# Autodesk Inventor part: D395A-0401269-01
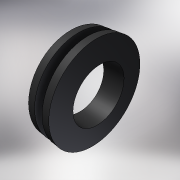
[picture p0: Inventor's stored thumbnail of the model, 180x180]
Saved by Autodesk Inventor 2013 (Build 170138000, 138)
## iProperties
Created: 2002-06
Part Number: D395A-0401269-01
Material: Rubber
Document SubType Name: Modeling
Designer: PVitaliy
Density: 0.93 g/cm^3
Mass: 3.61777 g
Surface Area: 34.5575 cm^2
Volume: 3.89008 cm^3
Author: PVitaliy
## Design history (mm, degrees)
derived "D395A-0401269.ipt"
body "Solid1"
tag "TaggingFeature2"
feature "DerivedBody::D395A-0401269.ipt" dims "d0" = 10
